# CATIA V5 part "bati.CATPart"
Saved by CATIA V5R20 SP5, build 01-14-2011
Part number: bati
Bounding box of the stored display mesh (mm): x -443.815 to -73.815, y -100 to 30, z -130 to 20
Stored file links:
  F:\iao\catia\projet iao\bati.CATPart
  F:\iao\catia\projet iao\fhartmann.CATProduct
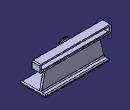
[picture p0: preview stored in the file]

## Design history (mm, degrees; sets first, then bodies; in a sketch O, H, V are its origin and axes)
External parameters (linked from other documents)
  External.bati_longueur_rail_ext = 370 mm
  External.bati_largeur_rail_ext = 40 mm
  External.bati_longueur_rail_int = 350 mm
  External.bati_largeur_plateau = 100 mm
  External.bati_epaisseur_languette = 10 mm
  External.bielle_diametre_int = 10 mm
Set1
  Plane1: linked copy from another document
  Point1 to Point4: linked copy from another document
  Plane2: linked copy from another document
  Point5: linked copy from another document
  Point6: linked copy from another document
  Plane3: linked copy from another document
  Point7 to Point12: linked copy from another document
  Plane4: linked copy from another document
  Point13 to Point15: linked copy from another document
Body1 (main body)
  Sketch1 on Plane1, origin (-258.8149, 0, 0), H (0, 1, 0), V (0, 0, 1)
    line L1 (-20, 20) -> (20, 20)
    line L2 (20, 20) -> (20, -20)
    line L3 (20, -20) -> (-20, -20)
    line L4 (-20, -20) -> (-20, 20)
    point P2 (20, 20)
    point P4 (-20, -20)
    reference projected point E1 (20, 20) from Point1
    reference projected point E2 (-20, -20) from Point2
    distance L2 L4 = 40 {= External.bati_largeur_rail_ext}
    parallelism: L1 L3
    perpendicularity: L1 L4
    coincidence: E1 P2, E2 P4
  Pad1: profile Sketch1, direction (1, 0, 0), length 185 {= External.bati_longueur_rail_ext /2}, opposite side length 185 {= External.bati_longueur_rail_ext /2}
  Sketch2 on Plane1, origin (-258.8149, 0, 0), H (0, 1, 0), V (0, 0, 1)
    line L1 (-15, 15) -> (15, 15)
    line L2 (15, 15) -> (15, -15)
    line L3 (15, -15) -> (-15, -15)
    line L4 (-15, -15) -> (-15, 15)
    point P2 (15, 15)
    point P4 (-15, -15)
    reference projected line E1 (20, 20) -> (-20, 20) from edge [face of Pad1 from Sketch1.L1 | end face of Pad1]
    reference projected point E2 (15, 15) from Point3
    reference projected point E3 (-15, -15) from Point4
    parallelism: L1 L3, L3 E1, L2 L4
    perpendicularity: L1 L4
    coincidence: P2 E2, P4 E3
  Pocket1: profile Sketch2, direction (-1, 0, 0), length 175 {= External.bati_longueur_rail_int /2}, opposite side length 175 {= External.bati_longueur_rail_int /2}
  Sketch3 on Plane2, origin (0, 20, 0), H (-1, 0, 0), V (0, 0, 1)
    line L1 (83.8149, 13) -> (433.8149, 13)
    line L2 (433.8149, 13) -> (433.8149, -13)
    line L3 (433.8149, -13) -> (83.8149, -13)
    line L4 (83.8149, -13) -> (83.8149, 13)
    point P2 (433.8149, 13)
    point P4 (83.8149, -13)
    reference projected line E1 (185, 20) -> (-185, 20) from edge [face of Pad1 from Sketch1.L1 | face of Pad1 from Sketch1.L2]
    reference projected point E2 (433.8149, 13) from Point5
    reference projected point E3 (83.8149, -13) from Point6
    parallelism: L1 L3, L3 E1, L2 L4
    perpendicularity: L1 L2
    coincidence: P2 E2, P4 E3
  Pocket2: profile Sketch3, direction (0, -1, 0), length 40 {= External.bati_largeur_rail_ext}
  Fillet1: radius 5, on edge [face of Pad1 from Sketch1.L1 | end face of Pad1]; edge [face of Pad1 from Sketch1.L3 | end face of Pad1]; edge [start face of Pad1 | face of Pad1 from Sketch1.L1]; edge [start face of Pad1 | face of Pad1 from Sketch1.L3]
  Sketch4 on Plane3, origin (0, 0, 0), H (-1, 0, 0), V (0, 0, 1)
    line L1 (397.5649, -20) -> (420.6899, -120)
    point P1 (397.5649, -20)
    point P2 (420.6899, -120)
    line L2 (96.9399, -120) -> (420.6899, -120)
    point P3 (96.9399, -120)
    point P4 (420.6899, -120)
    line L3 (120.0649, -20) -> (397.5649, -20)
    point P5 (120.0649, -20)
    point P6 (397.5649, -20)
    line L4 (120.0649, -20) -> (96.9399, -120)
    point P7 (120.0649, -20)
    point P8 (96.9399, -120)
    reference projected point E1 (397.5649, -20) from Point7
    reference projected point E2 (120.0649, -20) from Point8
    reference projected point E3 (397.5649, -20) from Point7
    reference projected point E4 (420.6899, -120) from Point9
    reference projected point E5 (420.6899, -120) from Point9
    reference projected point E6 (96.9399, -120) from Point10
    reference projected point E7 (96.9399, -120) from Point10
    reference projected point E8 (120.0649, -20) from Point8
    coincidence: P6 E1, P5 E2, P1 E3, P2 E4, P4 E5, P3 E6, P8 E7, P7 E8, P1 P6, P2 P4, P3 P8, P5 P7
  Pad2: profile Sketch4, direction (0, 1, 0), length 5, opposite side length 5
  Sketch5 on Plane3, origin (0, 0, 0), H (-1, 0, 0), V (0, 0, 1)
    point P1 (91.9399, -120)
    line L1 (91.9399, -120) -> (425.6899, -120)
    line L2 (425.6899, -120) -> (425.6899, -130)
    line L3 (425.6899, -130) -> (91.9399, -130)
    line L4 (91.9399, -130) -> (91.9399, -120)
    point P3 (425.6899, -130)
    reference projected line E1 (175, 13) -> (-175, 13) from edge [face of Pad1 from Sketch1.L2 | face of Pocket2 from Sketch3.L1]
    reference projected point E2 (91.9399, -120) from Point11
    reference projected point E3 (425.6899, -130) from Point12
    parallelism: L1 L3, L3 E1, L2 L4
    perpendicularity: L1 L2
    coincidence: P1 E2, P3 E3
  Pad3: profile Sketch5, direction (0, 1, 0), length 30 {= External.bati_largeur_plateau /100*30}, opposite side length 100 {= External.bati_largeur_plateau}
  Fillet2: radius 5, on edge [face of Pad3 from Sketch5.L4 | face of Pad3 from Sketch5.L1]; edge [face of Pad3 from Sketch5.L1 | end face of Pad3]; edge [start face of Pad3 | face of Pad3 from Sketch5.L1]; edge [face of Pad3 from Sketch5.L1 | face of Pad3 from Sketch5.L2]
  Fillet3: radius 5, on edge [face of Pad1 from Sketch1.L3 | face of Pad2 from Sketch4.L1]; edge [face of Pad1 from Sketch1.L3 | end face of Pad2]; edge [face of Pad2 from Sketch4.L4 | face of Pad1 from Sketch1.L3]; edge [start face of Pad2 | face of Pad1 from Sketch1.L3]; edge [start face of Pad2 | face of Pad3 from Sketch5.L1]; edge [face of Pad3 from Sketch5.L1 | end face of Pad2]
  Sketch6 on Plane4, origin (0, -34.22, 0), H (-1, 0, 0), V (0, 0, 1)
    point P1 (233.8149, 20)
    line L1 (233.8149, 20) -> (283.8149, 20)
    line L2 (283.8149, 20) -> (283.8149, -120)
    line L3 (283.8149, -120) -> (233.8149, -120)
    line L4 (233.8149, -120) -> (233.8149, 20)
    point P3 (283.8149, -120)
    reference projected line E1 (185, -20) -> (-185, -20) from edge [face of Pad1 from Sketch1.L2 | face of Pad1 from Sketch1.L3]
    reference projected point E2 (233.8149, 20) from Point13
    reference projected point E3 (283.8149, -120) from Point14
    parallelism: L1 L3, L3 E1, L2 L4
    perpendicularity: L1 L2
    coincidence: P1 E2, P3 E3
  Pad4: profile Sketch6, direction (0, -1, 0), length 10 {= External.bati_epaisseur_languette}
  Fillet4: radius 20, on edge [face of Pad4 from Sketch6.L4 | face of Pad3 from Sketch5.L1]; edge [face of Pad3 from Sketch5.L1 | face of Pad4 from Sketch6.L2]
  Fillet5: radius 20, on edge [face of Pad4 from Sketch6.L1 | face of Pad4 from Sketch6.L4]; edge [face of Pad4 from Sketch6.L2 | face of Pad4 from Sketch6.L1]
  Sketch7 on start face of Pad4, origin (0, -34.22, 0), H (1, 0, 0), V (0, 0, -1)
    point P1 (-258.8149, 0)
    reference projected point E1 (-258.8149, 0) from Point15
    coincidence: E1 P1
  Hole1: placed by Sketch7, at (-258.8149, -34.22, 0) direction (0, -1, 0), diameter 10 {= External.bielle_diametre_int}, depth 10 {= External.bati_epaisseur_languette}
  Fillet6: radius 3, on edge [end face of Pad4 | face of Pad4 from Sketch6.L2]; edge [face of Pad4 from Sketch6.L2 | start face of Pad4]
